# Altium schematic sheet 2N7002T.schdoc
size 127 x 101 mm
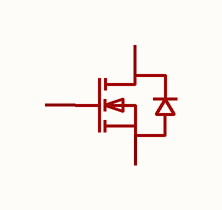
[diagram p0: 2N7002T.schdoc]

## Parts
Q?  2n7002t_c40106  [SC-75-3_L1.6-W0.8-P1.00-LS1.7-BR]  (value not drawn)

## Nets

Not connected (* = marked no-connect by the designer): Q? 1(G) 2(S) 3(D)

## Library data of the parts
Q? = 2n7002t_c40106: 数量:1个N沟道;漏源电压(Vdss):60V;连续漏极电流(Id):115mA;导通电阻(RDS(on)):5Ω@10V;耗散功率(Pd):150mW;阈值电压(Vgs(th)):2.5V;; Manufacturer: CJ(江苏长电/长晶); AddInBom: yes; ModelId: c91d337f73514bed9e4f5de3964a5f78; ModelName: SC-75-3_L1.6-W0.8-H0.9-LS1.6-P1.0; ModelTransform: 63.48633,62.992,0,180,0,0,0,0.005,0; Number: 1个N沟道; Drain to Source Voltage: 60V; Current - Continuous Drain(Id): 115mA; RDS(on): 5Ω@10V; Pd - Power Dissipation: 150mW; Gate Threshold Voltage (Vgs(th)): 2.5V; Input Capacitance(Ciss): 50pF; Reverse Transfer Capacitance (Crss@Vds): 5pF; Type: N沟道; Output Capacitance(Coss): 25pF; Vgs: ±20V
